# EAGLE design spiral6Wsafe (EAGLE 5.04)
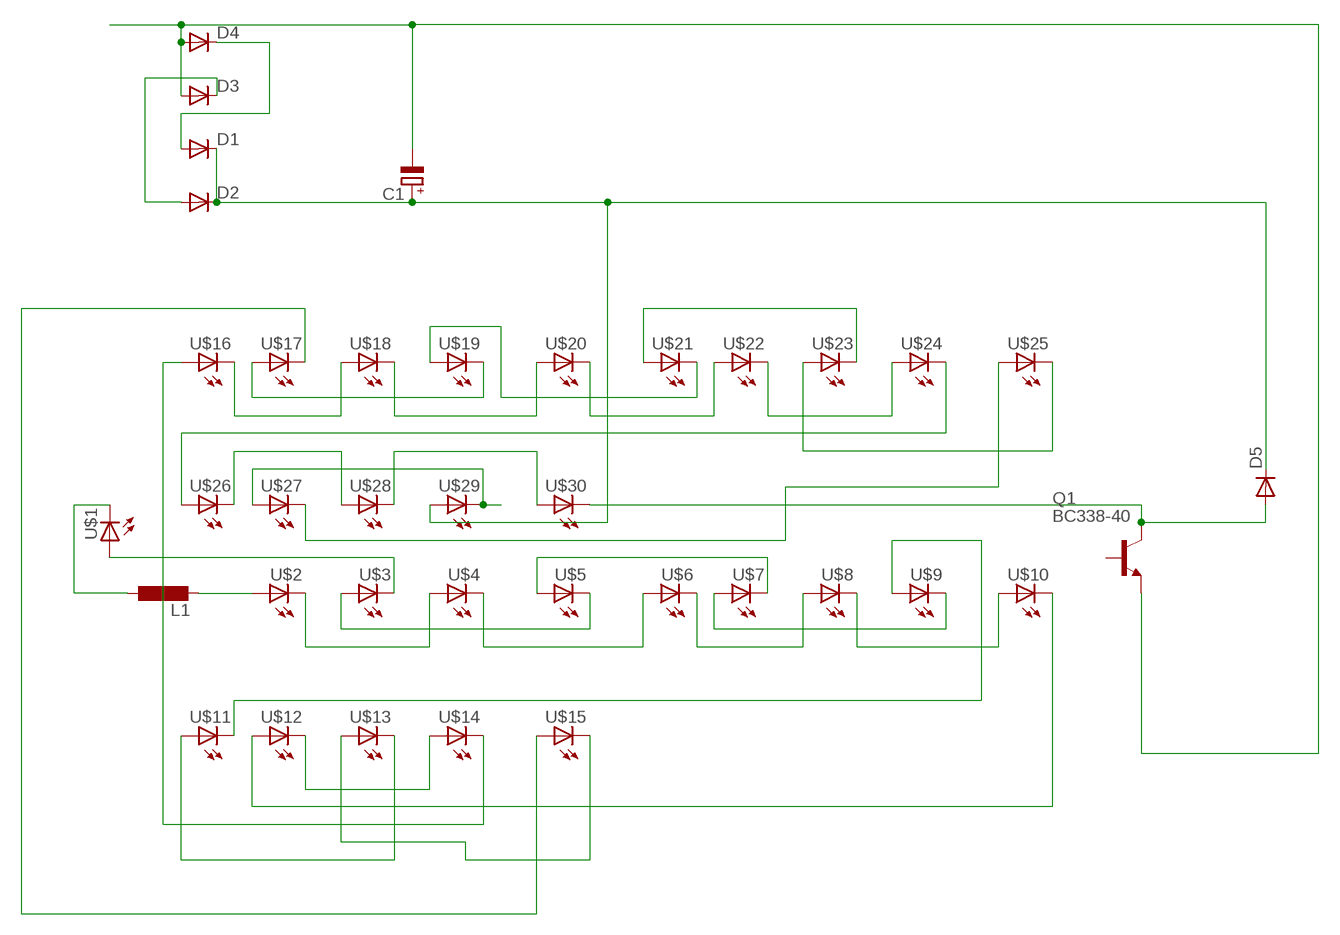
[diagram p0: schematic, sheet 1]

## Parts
C1  CPOL-EUE5-8.5  [E5-8,5]
D1  DIODE-D-5  [D-5]
D2  DIODE-D-5  [D-5]
D3  DIODE-D-5  [D-5]
D4  DIODE-D-5  [D-5]
D5  DIODE-D-2.5  [D-2.5]
L1  L-EU0207/10  [0207/10]
Q1  BC338-40  [TO92-EBC]
U$1  LED5MM  [LED5MM]
U$2  LED5MM  [LED5MM]
U$3  LED5MM  [LED5MM]
U$4  LED5MM  [LED5MM]
U$5  LED5MM  [LED5MM]
U$6  LED5MM  [LED5MM]
U$7  LED5MM  [LED5MM]
U$8  LED5MM  [LED5MM]
U$9  LED5MM  [LED5MM]
U$10  LED5MM  [LED5MM]
U$11  LED5MM  [LED5MM]
U$12  LED5MM  [LED5MM]
U$13  LED5MM  [LED5MM]
U$14  LED5MM  [LED5MM]
U$15  LED5MM  [LED5MM]
U$16  LED5MM  [LED5MM]
U$17  LED5MM  [LED5MM]
U$18  LED5MM  [LED5MM]
U$19  LED5MM  [LED5MM]
U$20  LED5MM  [LED5MM]
U$21  LED5MM  [LED5MM]
U$22  LED5MM  [LED5MM]
U$23  LED5MM  [LED5MM]
U$24  LED5MM  [LED5MM]
U$25  LED5MM  [LED5MM]
U$26  LED5MM  [LED5MM]
U$27  LED5MM  [LED5MM]
U$28  LED5MM  [LED5MM]
U$29  LED5MM  [LED5MM]
U$30  LED5MM  [LED5MM]

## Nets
N$1: C1.- D3.A D4.A Q1.E
N$2: U$2.K(C) U$4.A
N$3: U$4.K(C) U$6.A
N$4: U$6.K(C) U$8.A
N$5: U$8.K(C) U$10.A
N$6: U$1.A U$3.K(C)
N$7: U$3.A U$5.K(C)
N$8: U$5.A U$7.K(C)
N$9: U$7.A U$9.K(C)
N$10: U$10.K(C) U$12.A
N$11: U$12.K(C) U$14.A
N$12: U$14.K(C) U$16.A
N$13: U$16.K(C) U$18.A
N$14: U$18.K(C) U$20.A
N$15: U$20.K(C) U$22.A
N$16: U$22.K(C) U$24.A
N$17: U$24.K(C) U$26.A
N$18: U$26.K(C) U$28.A
N$19: U$28.K(C) U$30.A
N$20: C1.+ D1.C D2.C D5.C U$29.A
N$21: L1.2 U$2.A
N$22: L1.1 U$1.K(C)
N$23: U$27.A U$29.K(C)
N$24: U$25.A U$27.K(C)
N$25: D1.A D4.C
N$26: D2.A D3.C
N$27: U$9.A U$11.K(C)
N$29: U$11.A U$13.K(C)
N$30: U$13.A U$15.K(C)
N$31: U$15.A U$17.K(C)
N$32: U$17.A U$19.K(C)
N$33: U$19.A U$21.K(C)
N$34: U$21.A U$23.K(C)
N$35: U$23.A U$25.K(C)
N$36: D5.A Q1.C U$30.K(C)
Unconnected: Q1.B

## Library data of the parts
C1 = rcl-2:CPOL-EU: POLARIZED CAPACITOR, European symbol
D1-D5 = diode-1:DIODE-: DIODE
L1 = rcl-2:L-EU: INDUCTOR, European symbol
Q1 = transistor-npn:BC338*: NPN Transistor
U$1-U$30 = led(2):LED: LED

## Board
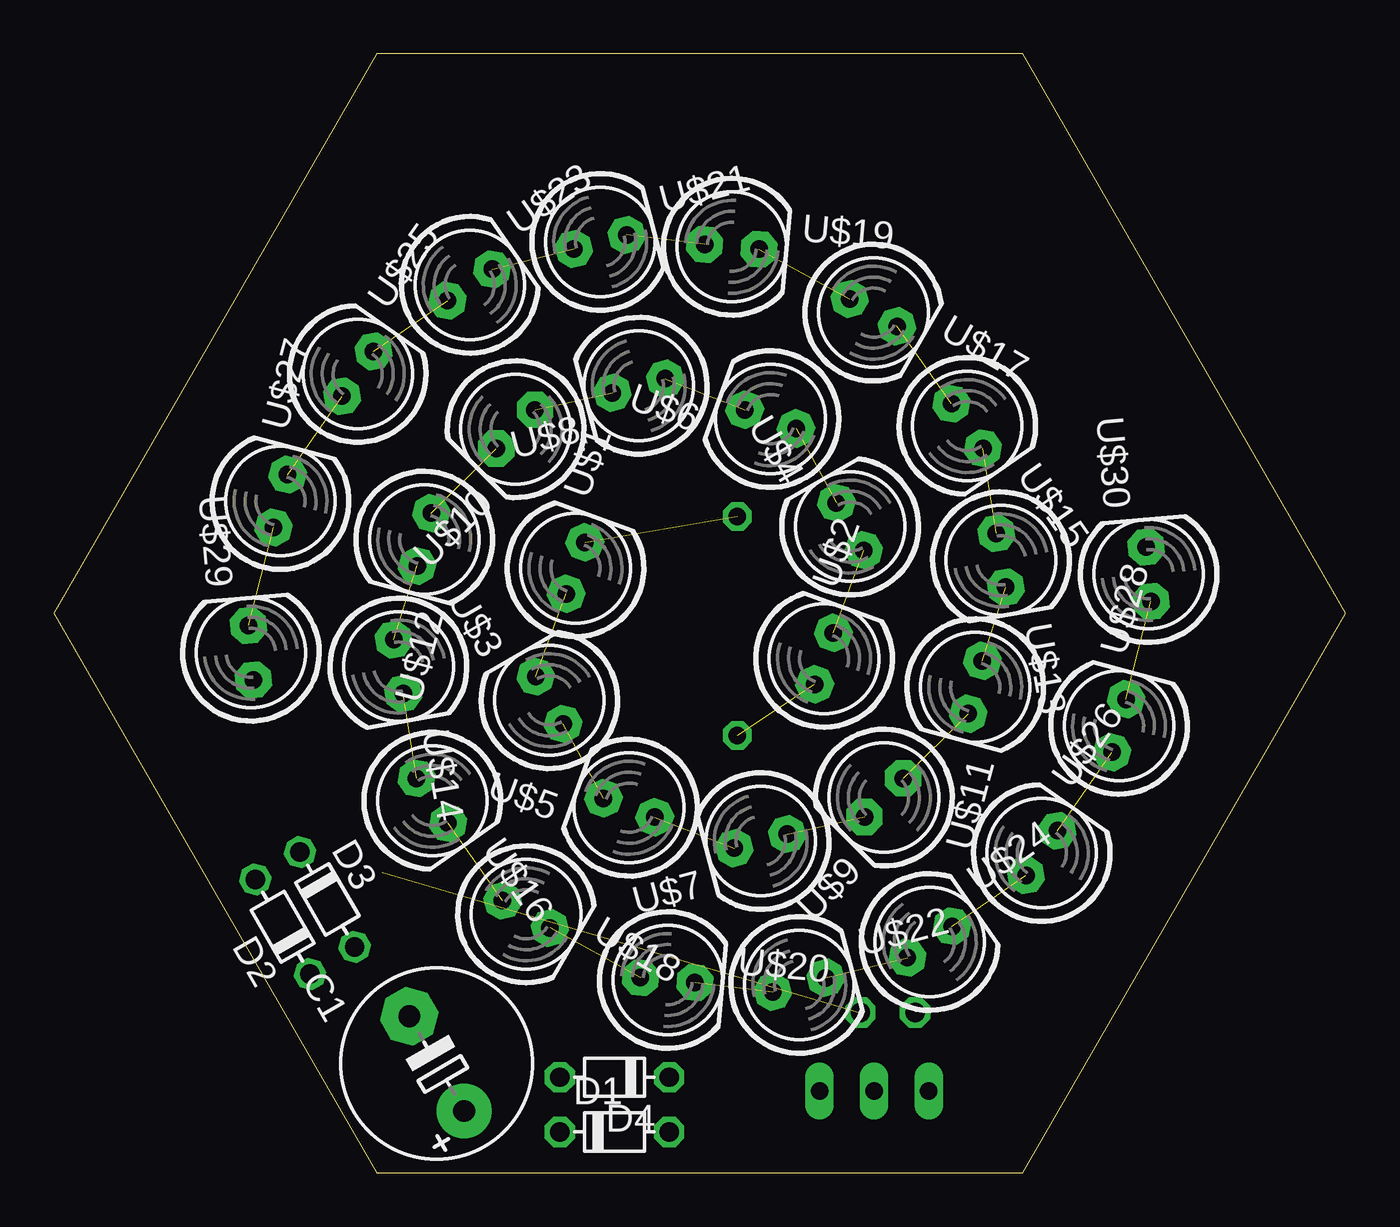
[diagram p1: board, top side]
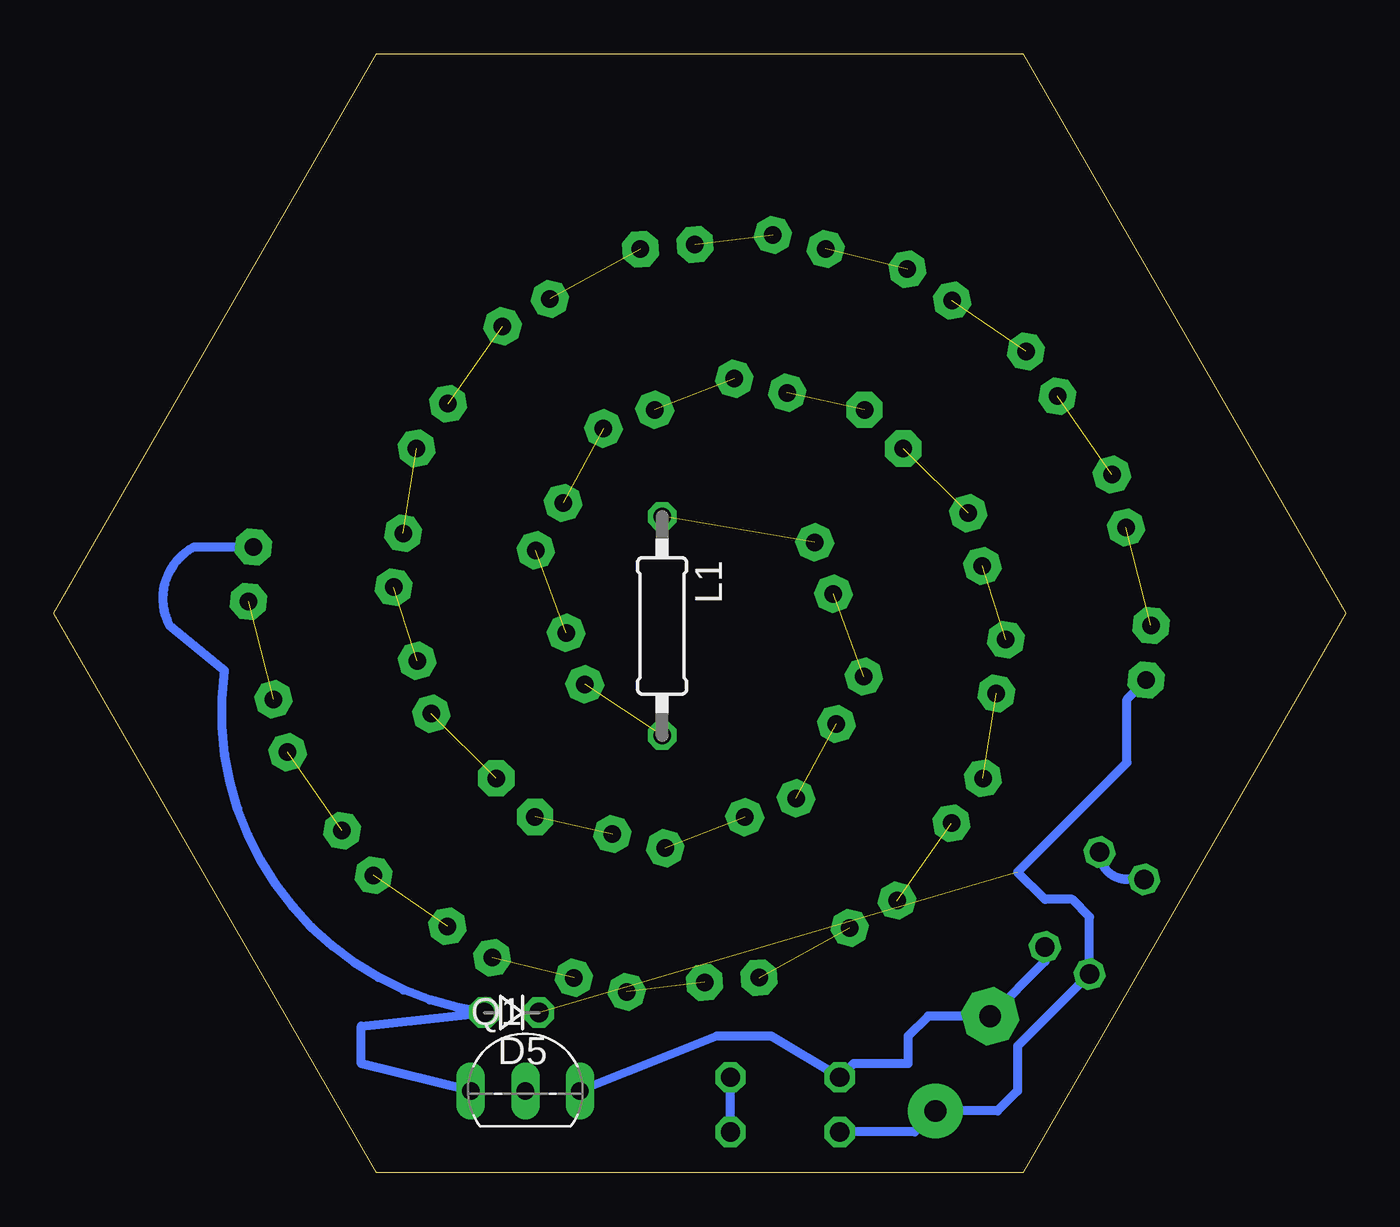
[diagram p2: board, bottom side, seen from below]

Size 60 x 51.96 mm. Coordinates in mm from the lower left corner, seen from the top.
Outline: 15,0 45,0 60,25.98 45,51.96 15,51.96 0,25.98 15,0
Copper layers (1*16): Top 0.035mm / dielectric 1.5mm / Bottom 0.035mm
Design rules "default": minimum track width 10mil, minimum drill 24mil, track to track 8mil, track to pad 8mil, pad to pad 8mil, via to via 8mil, smd to smd 8mil, copper to edge 40mil, drill to drill 8mil, minimum pad ring 10mil, minimum via ring 8mil, stop-mask expansion 4mil, vias tented up to drill 0mil, thermal gap 10mil

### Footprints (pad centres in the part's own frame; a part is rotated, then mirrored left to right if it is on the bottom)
E5-8,5 = drill 1.016 pad 2.54 round: + -2.54,0 | drill 1.016 pad 2.54 octagon: - 2.54,0
D-5 = drill 0.9 octagon: A 2.54,0; C -2.54,0
D-2.5 = drill 0.9 octagon: A 1.27,0; C -1.27,0
0207/10 = drill 0.813 octagon: 1 -5.08,0; 2 5.08,0
TO92-EBC = drill 0.813 long: B 0,-1.27; C -2.54,-1.27; E 2.54,-1.27
LED5MM = drill 0.813 pad 1.676 octagon: A -1.27,0; K 1.27,0

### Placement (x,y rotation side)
C1  17.78,5.08 120 top
D1  26.04,1.91 0 top
D2  10.62,11.43 120 top
D3  12.7,12.7 300 top
D4  26.04,4.45 180 top
D5  38.73,7.45 180 bottom
L1  31.75,25.4 270 bottom
Q1  38.1,5.08 0 bottom
U$1  24.23,28.08 70 top
U$2  35.77,23.88 70 top
U$3  23.02,21.95 120 top
U$4  36.98,30.01 120 top
U$5  26.72,16.96 160 top
U$6  33.28,35 160 top
U$7  32.83,15.41 195 top
U$8  27.17,36.55 195 top
U$9  38.55,17.43 225 top
U$10  21.45,34.53 225 top
U$11  42.8,22.55 255 top
U$12  17.2,29.41 255 top
U$13  43.99,28.45 280 top
U$14  16.01,23.51 280 top
U$15  42.42,34.68 305 top
U$16  17.58,17.28 305 top
U$17  38.06,39.95 330 top
U$18  21.94,12.01 330 top
U$19  31.49,43 355 top
U$20  28.51,8.96 355 top
U$21  25.38,43.23 14.9 top
U$22  34.62,8.73 14.9 top
U$23  19.32,41.23 35 top
U$24  40.68,10.73 35 top
U$25  14.12,37.1 54.9 top
U$26  45.88,14.86 54.9 top
U$27  10.53,31.2 75 top
U$28  49.47,20.76 75 top
U$29  9.15,24.16 95 top
U$30  50.85,27.8 95 top

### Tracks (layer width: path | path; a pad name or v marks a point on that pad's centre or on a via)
N$1
  Bottom 0.406: D3.A 13.97,9.82 C1.- 19.39,7.28 20.32,6.35 20.32,5.08 22.86,5.08 D4.A 26.67,6.35 29.21,6.35 Q1.E
N$2  (1 unrouted)
N$3  (1 unrouted)
N$4  (1 unrouted)
N$5  (1 unrouted)
N$6  (1 unrouted)
N$7  (1 unrouted)
N$8  (1 unrouted)
N$9  (1 unrouted)
N$10  (1 unrouted)
N$11  (1 unrouted)
N$12  (1 unrouted)
N$13  (1 unrouted)
N$14  (1 unrouted)
N$15  (1 unrouted)
N$16  (1 unrouted)
N$17  (1 unrouted)
N$18  (1 unrouted)
N$19  (1 unrouted)
N$20  (1 unrouted)
  Bottom 0.406: U$29.A 10.16,22 10.16,19.05 15.24,13.97 13.97,12.7 12.7,12.7 11.89,11.89 D2.C 15.24,5.88 15.24,3.81 16.17,2.88 C1.+ 20.02,1.91 D1.C
N$21  (1 unrouted)
N$22  (1 unrouted)
N$23  (1 unrouted)
N$24  (1 unrouted)
N$25
  Bottom 0.406: D1.A D4.C
N$26
  Bottom 0.406: D2.A 10.16,13.63 arc90 D3.C
N$27  (1 unrouted)
N$29  (1 unrouted)
N$30  (1 unrouted)
N$31  (1 unrouted)
N$32  (1 unrouted)
N$33  (1 unrouted)
N$34  (1 unrouted)
N$35  (1 unrouted)
N$36
  Bottom 0.406: U$30.K 53.48,29.07 arc-90 54.61,25.4 52.07,23.32 arc-90 D5.A 45.72,6.82 45.72,5.08 Q1.C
